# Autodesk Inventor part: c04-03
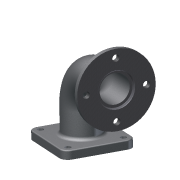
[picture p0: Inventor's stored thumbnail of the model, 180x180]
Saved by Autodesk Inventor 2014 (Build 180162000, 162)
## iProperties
Created: 2010-11
Part Number: c04-03
Material: Iron, Gray Cast ASTM A48 Grade 25
Document SubType Name: Modeling
Designer: Thom Tremblay
Density: 6.91439 g/cm^3
Appearance: Aluminum Cast
Author: Thom Tremblay
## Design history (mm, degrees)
sketch "Sketch1"
  geometry: L1 (60, 60)-(60, -60); L2 (60, -60)-(-60, -60); L3 (-60, -60)-(-60, 60); L4 (-60, 60)-(60, 60); C1 r 33 at (0, 0); C2 r 25 at (0, 0); 2 further points
  constraints: 8 end point, 3 coincident, 2 centre point, 1 horizontal, 9 other
  dimensions: "d0" = 120 distance of L3.end L1.start; "d8" = 8 radial gap between concentric circles of C1 C2; "d17" = 50 diameter of C2
extrude "Extrusion1" new body sketch "Sketch1" distance "d1" = 15; taper "d2" = 0 deg
sketch "Sketch2"
  geometry: L1 (0, 0)-(0, 60); L2 (-60, 120)-(-120, 120); A1 r 60 centre (-60, 60) between (0, 60) and (-60, 120)
  constraints: 4 end point, 2 point on circle, 2 tangent, 1 centre point, 1 vertical
  dimensions: "d3" = 60 distance of L1.start L1.end; "d4" = 60 distance of L2.start L2.end; "d5" = 90 deg angle of L1 L2; "d6" = 60 radius of A1
workplane "Work Plane1"
sketch "Sketch3"
  geometry: C1 r 65 at (0, 0); 2 further points
  constraints: 1 centre point, 1 coincident
  dimensions: "d9" = 130 diameter of C1
extrude "Extrusion2" join sketch "Sketch3" distance "d10" = 10; taper "d11" = 0 deg
sweep "Sweep1" dims "d12" = 0
sweep "Sweep2" dims "d13" = 0
fillet "Fillet1" dims "d14" = 14, "d15" = 6, "d16" = 2
hole "Hole1" diameter "d20" = 11; stored, may be unused: countersink angle "d24" = 90 deg, drill point angle "d26" = 118 deg; dims "d18" = 10, "d19" = 10, "d21" = 6, "d22" = 20, "d23" = 2, "d25" = 8
hole "Hole2" diameter "d29" = 11; stored, may be unused: countersink angle "d33" = 90 deg, drill point angle "d35" = 118 deg; dims "d27" = 10, "d28" = 10, "d30" = 6, "d31" = 20, "d32" = 2, "d34" = 8
hole "Hole3" diameter "d38" = 11; stored, may be unused: countersink angle "d42" = 90 deg, drill point angle "d44" = 118 deg; dims "d36" = 10, "d37" = 10, "d39" = 6, "d40" = 20, "d41" = 2, "d43" = 8
hole "Hole4" diameter "d47" = 11; stored, may be unused: countersink angle "d51" = 90 deg, drill point angle "d53" = 118 deg; dims "d45" = 10, "d46" = 10, "d48" = 6, "d49" = 20, "d50" = 2, "d52" = 8
sketch "Sketch4" dims "d54" = 100
  geometry: L1 (0, 50)-(50, 0); L2 (50, 0)-(0, -50); L3 (0, -50)-(-50, 0); L4 (-50, 0)-(0, 50); C1 r 65 at (0, 0) reference; 3 further points
  constraints: 8 end point, 2 coincident, 1 vertical alignment, 11 other
hole "Hole5" sketch "Sketch4" at (0, 50), (50, 0), (0, -50), (-50, 0) diameter "d55" = 11.835; stored, may be unused: countersink angle "d59" = 90 deg, drill point angle "d61" = 118 deg; dims "d56" = 6, "d57" = 20, "d58" = 2, "d60" = 8
sketch "Sketch5"
  geometry: C1 r 65 at (0, 0) reference; C2 r 30 at (0, 0); 1 further point
  constraints: 1 centre point, 1 coincident
  dimensions: "d62" = 60 diameter of C2
extrude "Extrusion3" cut sketch "Sketch5" distance "d63" = 6; taper "d64" = 0 deg
sketch "Sketch6"
  geometry: C1 r 25 at (0, 0) reference; C2 r 30 at (0, 0); C3 r 33 at (0, 0)
  constraints: 2 centre point, 1 coincident
  dimensions: "d65" = 60 diameter of C2; "d66" = 3 radial gap between concentric circles of C3 C2
extrude "Extrusion4" cut sketch "Sketch6" distance "d67" = 3; taper "d68" = 0 deg
fillet "Fillet2" dims "d69" = 0.5
chamfer "Chamfer1" distance "d70" = 2; stored, may be unused: second distance "d71" = 2, angle "d72" = 45 deg
chamfer "Chamfer2" distance "d73" = 1; stored, may be unused: second distance "d74" = 2, angle "d75" = 45 deg
fillet "Fillet3" dims "d76" = 0.5
body "Solid1"
